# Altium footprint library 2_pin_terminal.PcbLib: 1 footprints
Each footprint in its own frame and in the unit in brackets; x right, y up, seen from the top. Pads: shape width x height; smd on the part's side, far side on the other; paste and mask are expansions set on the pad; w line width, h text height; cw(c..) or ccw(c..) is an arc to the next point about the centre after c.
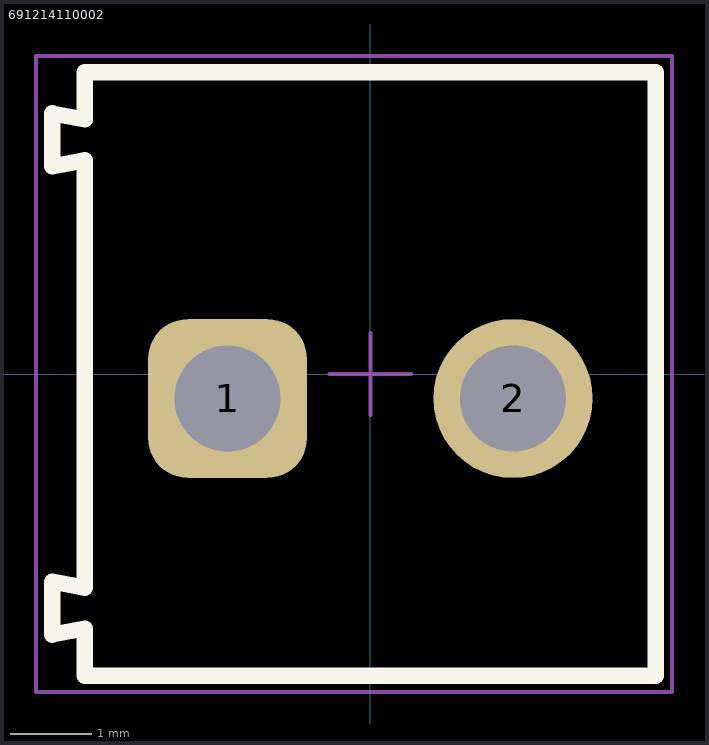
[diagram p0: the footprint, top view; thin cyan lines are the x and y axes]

## 691214110002 [mm] "3.50 mm Horizontal Entry Modular, 2p"
height 8.5
pads (2):
  rrect50% 1.95x1.95 hole 1.3: 1(-1.75,-0.3)
  round 1.95 hole 1.3: 2(1.75,-0.3)
Top Overlay:
  lines w0.2: -3.9,-3.195 -3.5,-3.12 -3.5,-3.7 3.5,-3.7 3.5,3.7 -3.5,3.7 -3.5,3.12 -3.9,3.195 -3.9,2.545 -3.5,2.62 -3.5,-2.62 -3.9,-2.545 -3.9,-3.195
Top Designator:
  text ".Designator" at -7.498,-0.5 h1.5
Top Component Outline:
  lines w0.1: -3.9,-3.195 -3.9,-2.545 -3.5,-2.62 -3.5,2.62 -3.9,2.545 -3.9,3.195 -3.5,3.12 -3.5,3.7 3.5,3.7 3.5,-3.7 -3.5,-3.7 -3.5,-3.12 -3.9,-3.195
Top 3D Body:
  lines w0.1: -3.9,-3.195 -3.5,-3.12 -3.5,-3.7 3.5,-3.7 3.5,3.7 -3.5,3.7 -3.5,3.12 -3.9,3.195 -3.9,2.545 -3.5,2.62 -3.5,-2.62 -3.9,-2.545 -3.9,-3.195
Top Courtyard:
  lines w0.05: -4.1,-3.9 3.7,-3.9 3.7,3.9 -4.1,3.9 -4.1,-3.9
Top Component Center:
  lines w0.05: -0.5,0 0.5,0 ; 0,-0.5 0,0.5
3D body "691214110002.stp": height 8.55, standoff -3.65, extent -3.95,-3.7 3.5,3.7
